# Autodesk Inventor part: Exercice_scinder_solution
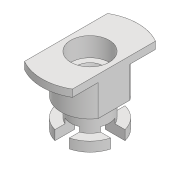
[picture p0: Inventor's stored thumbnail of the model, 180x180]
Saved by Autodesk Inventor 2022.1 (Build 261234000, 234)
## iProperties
Created: 2018-06
Part Number: Exercice_scinder_solution
Material: Générique
Document SubType Name: Modeling
Designer: Fabian Perrée
Density: 1 g/cm^3
Appearance: Par défaut
Mass: 0.914032 g
Surface Area: 11.7142 cm^2
Volume: 0.914032 cm^3
Author: Fabian Perrée
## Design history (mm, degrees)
node "Annotations"
  node "Cote linéaire 1" dims "d15" = 3, "d30" = 10 (derived)
sketch "Esquisse1"
  geometry: L1 (0, 0)-(0, 14); L2 (0, 14)-(10, 14); L3 (10, 14)-(10, 12.5); L4 (10, 12.5)-(6, 12.5); L5 (6, 12.5)-(6, 6); L6 (6, 6)-(4, 6); L7 (4, 6)-(4, 2); L8 (4, 2)-(6, 2); L9 (6, 2)-(6, 0); L10 (6, 0)-(0, 0); L11 (4, 14)-(4, 10); L12 (4, 10)-(2.25, 10); L13 (2.25, 10)-(2.25, 3); L14 (2.25, 3)-(0, 3)
  constraints: 28 end point, 12 perpendicular, 2 point on line, 2 vertical, 1 collinear
  dimensions: "d0" = 14 distance of L1.start L1.end; "d2" = 1.5 distance of L2.end L3.end; "d3" = 20 diameter of L3 L1; "d5" = 12 diameter of L5 L1; "d6" = 8 diameter of L7 L1; "d7" = 6.5 distance of L4.end L5.end; "d8" = 4 distance of L6.end L7.end; "d9" = 2 distance of L8.end L9.end (derived); "d10" = 8 diameter of L11 L1; "d11" = 4.5 diameter of L13 L1; "d12" = 4 distance of L11.start L11.end; "d13" = 3 distance between parallel lines of L10 L14
revolve "Révolution1" sketch "Esquisse1" stored, may be unused: angle "d14" = 90 deg
sketch "Esquisse2"
  geometry: L1 (6, 1.5)-(0, 1.5); L2 (0, 1.5)-(0, -1.5); L3 (0, -1.5)-(6, -1.5); L4 (6, -1.5)-(6, 1.5); L5 (0, 0)-(10, 0); C1 r 6 at (0, 0) reference; 1 further point
  constraints: 10 end point, 2 parallel, 1 horizontal, 1 horizontal alignment, 1 midpoint, 1 perpendicular, 1 tangent, 2 other
  dimensions: "d15" = 3 distance of L3.end L1.start
extrude "Extrusion1" cut sketch "Esquisse2" distance "d16" = 3; taper "d17" = 0 deg
pattern_circular "Réseau circulaire1" dims angle "d19" = 360 deg
chamfer "Chanfrein1" distance "d21" = 0.5; stored, may be unused: second distance "d22" = 2, angle "d23" = 45 deg
sketch "Esquisse3"
  geometry: C1 r 2.25 at (0, 0); A1 r 2.25 centre (0, 0) between (-1.5, -1.677) and (1.5, -1.677) reference
  constraints: 1 centre point, 1 coincident, 1 concentric
extrude "Extrusion2" cut sketch "Esquisse3" extent not by distance; stored distance "d24" = 10; taper "d25" = 0 deg
node "Plan de construction1"
node "Plan de construction2"
feature "Scission3"
  node "Solide1"
feature "Scission4"
mirror "Symétrie1"
feature "Combiner1"
  node "Solide2"
node "Solide3"
other parameters: "d26" = 5, "d27" = 0, "d28" = 6.0975 (derived), "d29" = 7.71976 (derived)
